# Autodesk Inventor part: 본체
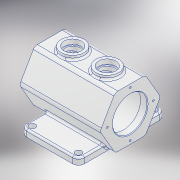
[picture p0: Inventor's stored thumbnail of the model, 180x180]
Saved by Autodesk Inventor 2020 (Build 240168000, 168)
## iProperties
Created: 2021-06
Part Number: 본체
Material: 알루미늄 6061
Document SubType Name: Modeling
Designer: 605-3
Density: 2.7 g/cm^3
Appearance: 알루미늄 - 평지
Mass: 1495.28 g
Surface Area: 1102.35 cm^2
Volume: 553.807 cm^3
Author: 605-3
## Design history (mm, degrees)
sketch "스케치1" dims "d0" = 105
  geometry: L1 (45.466, -26.25)-(0, -52.5); L2 (0, -52.5)-(-45.466, -26.25); L3 (-45.466, -26.25)-(-45.466, 26.25); L4 (-45.466, 26.25)-(0, 52.5); L5 (0, 52.5)-(45.466, 26.25); L6 (45.466, 26.25)-(45.466, -26.25); 3 further points
  constraints: 12 end point, 2 coincident, 1 vertical, 16 other
extrude "돌출1" new body sketch "스케치1" stored distance "d1" = 140; taper "d2" = 0 deg
node "작업 평면3"
sketch "스케치2"
  geometry: L1 (45, -75)-(-55, -75); L2 (-55, -75)-(-55, 75); L3 (-55, 75)-(45, 75); L4 (45, 75)-(45, -75); L5 (70, -26.25)-(70, -52.5) reference; L6 (-70, -52.5)-(-70, -26.25) reference; 1 further point
  constraints: 8 end point, 2 parallel, 1 horizontal, 1 perpendicular
  dimensions: "d4" = 25 distance between parallel lines of L4 L5; "d5" = 15 distance between parallel lines of L2 L6; "d6" = 150 distance of L3.end L1.start; "d7" = 75 distance from line of point (0, 0) L1
extrude "돌출2" join sketch "스케치2" distance "d8" = 12; taper "d9" = 0 deg
sketch "스케치3"
  geometry: C1 r 30 at (0, 0); 1 further point
  constraints: 1 centre point, 1 coincident
  dimensions: "d10" = 60 diameter of C1
extrude "돌출3" cut sketch "스케치3" distance "d11" = 12; taper "d12" = 0 deg
sketch "스케치4"
  geometry: C1 r 37.5 at (0, 0); 1 further point
  constraints: 1 centre point, 1 coincident
  dimensions: "d13" = 75 diameter of C1
extrude "돌출4" cut sketch "스케치4" distance "d14" = 116; taper "d15" = 0 deg
sketch "스케치5"
  geometry: C1 r 30 at (0, 0); 1 further point
  constraints: 1 centre point, 1 coincident
  dimensions: "d16" = 60 diameter of C1
extrude "돌출5" cut sketch "스케치5" distance "d17" = 12; taper "d18" = 0 deg
node "작업 평면5"
sketch "스케치7"
  geometry: L1 (70, -26.25)-(70, -52.5) reference; C1 r 20 at (30, 0); C2 r 20 at (-30, 0); 1 further point
  constraints: 2 centre point, 2 horizontal alignment
  dimensions: "d24" = 40 diameter of C1; "d25" = 40 diameter of C2; "d26" = 40 distance from line of C1.centre L1; "d27" = 60 distance of C2.centre C1.centre
extrude "돌출6" join sketch "스케치7" stored distance "d28" = 12; taper "d29" = 0 deg
sketch "스케치8"
  geometry: C1 r 20 at (0, 0) reference; C2 r 20 at (60, 0) reference; 3 further points
  constraints: 2 coincident
hole "구멍1" sketch "스케치8" at (0, 0), (60, 0) diameter "d30" = 25; stored, may be unused: countersink angle "d34" = 90 deg, drill point angle "d36" = 0 deg; dims "d31" = 6, "d32" = 30, "d33" = 8, "d35" = 32.25
fillet "모깎기1" dims "d37" = 10
sketch "스케치9"
  geometry: A1 r 10 centre (-35, -65) between (-45, -65) and (-35, -75) reference; A2 r 10 centre (45, -65) between (45, -75) and (55, -65) reference; A3 r 10 centre (45, 65) between (55, 65) and (45, 75) reference; A4 r 10 centre (-35, 65) between (-35, 75) and (-45, 65) reference; 5 further points
  constraints: 4 coincident
hole "구멍2" sketch "스케치9" at (-35, -65), (45, -65), (45, 65), (-35, 65) diameter "d38" = 11; stored, may be unused: countersink angle "d42" = 90 deg, drill point angle "d44" = 0 deg; dims "d39" = 6, "d40" = 30, "d41" = 8, "d43" = 32.25
sketch "스케치10" dims "d45" = 80
  geometry: 3 further points
  constraints: 2 vertical alignment, 1 coincident, 2 other
hole "구멍3" sketch "스케치10" at (0, 40) diameter "d46" = 3.242; stored, may be unused: countersink angle "d50" = 90 deg, drill point angle "d52" = 120 deg; dims "d47" = 8, "d48" = 30, "d49" = 8, "d51" = 10
sketch "스케치11"
  geometry: L1 (0, 0)-(-40, 0); L2 (0, 0)-(-28.284, 28.284); A1 r 40 centre (0, 0) between (-40, 0) and (-28.284, 28.284); 2 further points
  constraints: 4 end point, 2 coincident, 2 point on circle, 1 centre point, 1 horizontal
  dimensions: "d56" = 80 diameter of A1; "d58" = 45 deg angle of L2 L1
hole "구멍4" sketch "스케치11" at (-28.284, 28.284) diameter "d59" = 3.242; stored, may be unused: countersink angle "d63" = 90 deg, drill point angle "d65" = 120 deg; dims "d60" = 8, "d61" = 30, "d62" = 8, "d64" = 10
fillet "모깎기2" dims "d69" = 8
fillet "모깎기3" dims "d70" = 3
fillet "모깎기4" dims "d71" = 3
fillet "모깎기5" dims "d72" = 3
sketch "스케치12"
  geometry: L1 (-35, 72)-(45, 72) reference; L2 (45, 75)-(-35, 75) reference; L3 (-45, 65)-(-45, 32.293) reference; 2 further points
  constraints: 1 other
  dimensions: "d73" = 14 distance from line of point (5, 61) L2; "d74" = 50 distance from line of point (5, 61) L3
feature "엠보싱1" sketch "스케치12" dims "d75" = 0.5, "d76" = 0
fillet "모깎기6" dims "d77" = 5
chamfer "모따기1" distance "d78" = 1; stored, may be unused: second distance "d79" = 2, angle "d80" = 45 deg
node "솔리드1"
pattern_circular "원형 패턴1" dims angle "d54" = 360 deg
pattern_circular "원형 패턴2" dims angle "d67" = 360 deg
feature "A9D066F2-1C7D-4E18-AEED-F7BC21143FA4" dims "d38" = 11, "d39" = 6, "d40" = 30, "d41" = 8, "d42" = 90 deg, "d43" = 32.25, "d44" = 0
other parameters: "d23" = 52.5
